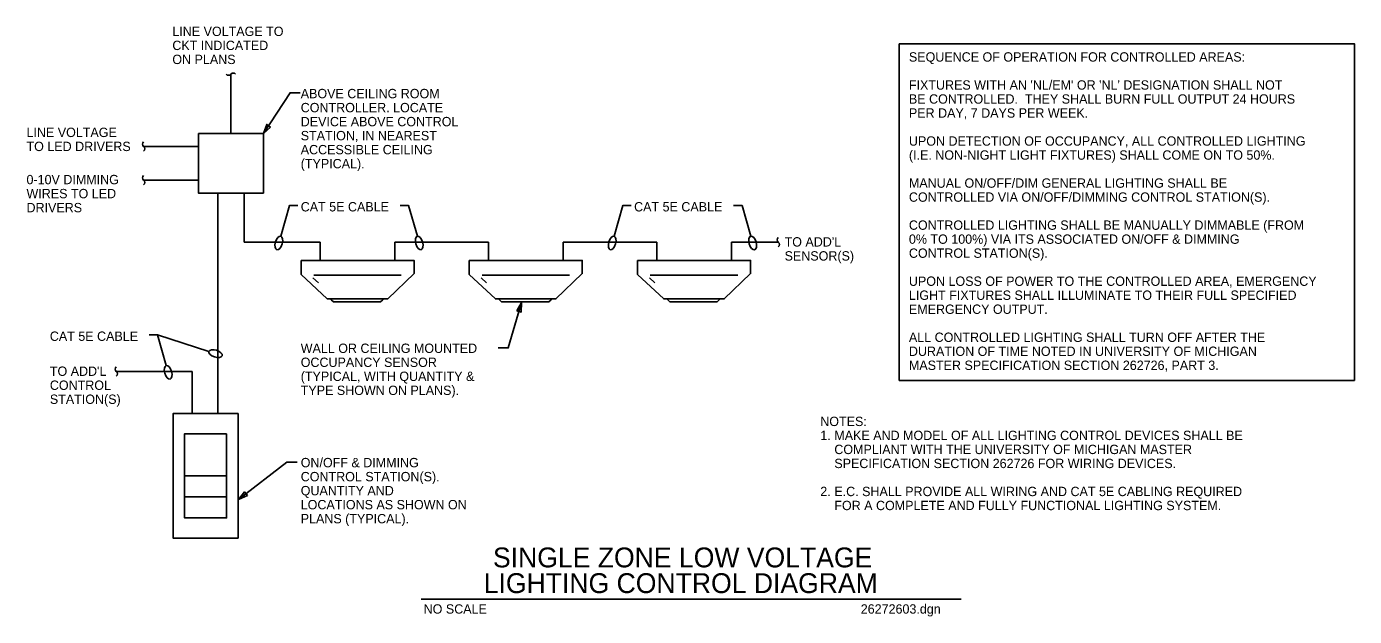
# Model space of a CAD drawing. Extents: x 10013.8 to 10108.5, y 10096.8 to 10138.9.
import ezdxf

# ---------------------------------------------------------------- set-up
doc = ezdxf.new("R2010")
doc.units = 0
for name, color, linetype in [('G-ANNO-CELL', 7, 'Continuous'), ('G-ANNO-TEXT', 7, 'Continuous'), ('G-DETL-LINE', 7, 'Continuous'), ('Level 3', 7, 'Continuous')]:
    doc.layers.add(name, color=color, linetype=linetype)

msp = doc.modelspace()

# ---------------------------------------------------------------- linework, layer by layer
at = {"layer": 'G-ANNO-CELL'}
msp.add_line((10041.898, 10098.023), (10080.422, 10098.023), dxfattribs=at)
at = {"layer": 'G-ANNO-TEXT'}
msp.add_line((10023.101, 10116.871), (10026.757, 10115.693), dxfattribs=at)
for points in [[(10075.997, 10137.655), (10108.458, 10137.655), (10108.458, 10113.63), (10075.997, 10113.63)], [(10031.167, 10131.701), (10030.653, 10131.244), (10030.892, 10131.889)], [(10048.716, 10118.601), (10049.063, 10119.194), (10049.036, 10118.508)], [(10029.513, 10105.412), (10028.885, 10105.132), (10029.308, 10105.674)]]:
    msp.add_lwpolyline(points, close=True, dxfattribs=at)
for points in [[(10033.28, 10134.151), (10032.551, 10134.151), (10030.653, 10131.244)], [(10033.106, 10126.106), (10032.505, 10126.106), (10031.885, 10123.918)], [(10040.407, 10126.106), (10041.009, 10126.106), (10041.628, 10123.918)], [(10056.882, 10126.106), (10056.281, 10126.106), (10055.661, 10123.918)], [(10064.183, 10126.106), (10064.784, 10126.106), (10065.404, 10123.918)], [(10047.402, 10115.946), (10048.112, 10115.946), (10049.063, 10119.194)], [(10022.499, 10116.871), (10023.101, 10116.871), (10023.72, 10114.683)], [(10033.054, 10107.791), (10032.325, 10107.791), (10028.885, 10105.132)]]:
    msp.add_lwpolyline(points, dxfattribs=at)
for centre, major_axis in [((10031.749, 10123.437), (-0.136, -0.481)), ((10041.764, 10123.437), (0.136, -0.481)), ((10055.525, 10123.437), (-0.136, -0.481)), ((10065.54, 10123.437), (0.136, -0.481)), ((10027.233, 10115.539), (0.476, -0.153)), ((10023.857, 10114.202), (0.136, -0.481))]:
    msp.add_ellipse(centre, major_axis=major_axis, ratio=0.5, dxfattribs=at)
at = {"layer": 'G-DETL-LINE'}
for p, q in [((10028.337, 10131.244), (10028.337, 10135.48)), ((10026.021, 10130.321), (10022.107, 10130.321)), ((10026.021, 10127.923), (10022.107, 10127.923)), ((10027.388, 10111.26), (10027.388, 10127)), ((10029.286, 10123.5), (10029.286, 10127)), ((10029.286, 10123.5), (10034.7, 10123.5)), ((10034.7, 10122.185), (10034.7, 10123.5)), ((10040.027, 10122.185), (10040.027, 10123.5)), ((10040.027, 10123.5), (10046.699, 10123.5)), ((10046.699, 10122.185), (10046.699, 10123.5)), ((10052.027, 10123.5), (10058.699, 10123.5)), ((10052.027, 10122.185), (10052.027, 10123.5)), ((10058.699, 10122.185), (10058.699, 10123.5)), ((10064.027, 10122.185), (10064.027, 10123.5)), ((10064.027, 10123.5), (10067.363, 10123.5)), ((10034.571, 10120.595), (10034.174, 10120.949)), ((10034.243, 10121.131), (10037.363, 10121.131)), ((10040.483, 10121.131), (10037.363, 10121.131)), ((10046.571, 10120.595), (10046.174, 10120.949)), ((10046.243, 10121.131), (10049.363, 10121.131)), ((10052.483, 10121.131), (10049.363, 10121.131)), ((10058.571, 10120.595), (10058.174, 10120.949)), ((10058.243, 10121.131), (10061.363, 10121.131)), ((10064.483, 10121.131), (10061.363, 10121.131)), ((10025.579, 10114.265), (10020.158, 10114.265)), ((10025.579, 10111.26), (10025.579, 10114.265)), ((10028.027, 10105.321), (10025.027, 10105.321))]:
    msp.add_line(p, q, dxfattribs=at)
for points in [[(10026.021, 10131.244), (10030.653, 10131.244), (10030.653, 10127), (10026.021, 10127)], [(10028.843, 10111.26), (10024.211, 10111.26), (10024.211, 10102.383), (10028.843, 10102.383)], [(10028.027, 10109.821), (10025.027, 10109.821), (10025.027, 10106.821), (10028.027, 10106.821)], [(10028.027, 10106.821), (10025.027, 10106.821), (10025.027, 10103.821), (10028.027, 10103.821)]]:
    msp.add_lwpolyline(points, close=True, dxfattribs=at)
for points in [[(10033.332, 10122.185), (10041.395, 10122.185), (10041.395, 10121.246), (10039.515, 10119.447), (10035.2, 10119.447), (10033.332, 10121.196), (10033.332, 10122.185)], [(10045.332, 10122.185), (10053.394, 10122.185), (10053.394, 10121.246), (10051.515, 10119.447), (10047.2, 10119.447), (10045.332, 10121.196), (10045.332, 10122.185)], [(10057.332, 10122.185), (10065.394, 10122.185), (10065.394, 10121.246), (10063.515, 10119.447), (10059.199, 10119.447), (10057.332, 10121.196), (10057.332, 10122.185)], [(10039.161, 10119.447), (10039.161, 10119.38), (10039.008, 10119.231), (10035.638, 10119.231), (10035.485, 10119.379), (10035.485, 10119.447)], [(10051.161, 10119.447), (10051.161, 10119.38), (10051.007, 10119.231), (10047.638, 10119.231), (10047.484, 10119.379), (10047.484, 10119.447)], [(10063.161, 10119.447), (10063.161, 10119.38), (10063.007, 10119.231), (10059.638, 10119.231), (10059.484, 10119.379), (10059.484, 10119.447)]]:
    msp.add_lwpolyline(points, dxfattribs=at)
for centre, start, end in [((10028.17, 10135.605), 216.8699, 323.1301), ((10028.504, 10135.355), 36.8699, 143.1301), ((10022.232, 10130.487), 126.8699, 233.1301), ((10021.982, 10130.154), 306.8699, 53.1301), ((10022.232, 10128.09), 126.8699, 233.1301), ((10021.982, 10127.757), 306.8699, 53.1301), ((10067.488, 10123.667), 126.8699, 233.1301), ((10067.238, 10123.333), 306.8699, 53.1301), ((10020.283, 10114.432), 126.8699, 233.1301), ((10020.033, 10114.099), 306.8699, 53.1301)]:
    msp.add_arc(centre, 0.208, start, end, dxfattribs=at)

# ---------------------------------------------------------------- texts
at = {"layer": 'G-ANNO-CELL'}
for s, height, p in [('SINGLE ZONE LOW VOLTAGE', 1.41667, (10047.02, 10100.289)), ('LIGHTING CONTROL DIAGRAM', 1.41667, (10046.365, 10098.455)), ('NO SCALE', 0.6667, (10042.078, 10096.988))]:
    msp.add_text(s, height=height, dxfattribs=at).set_placement(p)
at = {"layer": 'G-ANNO-TEXT'}
for s, height, p in [('LINE VOLTAGE TO ', 0.66667, (10024.156, 10138.201)), ('CKT INDICATED ', 0.66667, (10024.156, 10137.201)), ('ON PLANS', 0.6667, (10024.156, 10136.201)), ('SEQUENCE OF OPERATION FOR CONTROLLED AREAS:', 0.66667, (10076.685, 10136.376)), ("FIXTURES WITH AN 'NL/EM' OR 'NL' DESIGNATION SHALL NOT ", 0.66667, (10076.685, 10134.376)), ('ABOVE CEILING ROOM ', 0.66667, (10033.312, 10133.762)), ('BE CONTROLLED.  THEY SHALL BURN FULL OUTPUT 24 HOURS ', 0.66667, (10076.685, 10133.376)), ('CONTROLLER. LOCATE ', 0.66667, (10033.312, 10132.762)), ('PER DAY, 7 DAYS PER WEEK.', 0.66667, (10076.685, 10132.376)), ('DEVICE ABOVE CONTROL ', 0.66667, (10033.312, 10131.762)), ('LINE VOLTAGE ', 0.66667, (10013.755, 10130.993)), ('STATION, IN NEAREST ', 0.66667, (10033.312, 10130.762)), ('UPON DETECTION OF OCCUPANCY, ALL CONTROLLED LIGHTING ', 0.66667, (10076.685, 10130.376)), ('TO LED DRIVERS', 0.66667, (10013.755, 10129.993)), ('ACCESSIBLE CEILING ', 0.66667, (10033.312, 10129.762)), ('(I.E. NON-NIGHT LIGHT FIXTURES) SHALL COME ON TO 50%.', 0.66667, (10076.685, 10129.376)), ('(TYPICAL).', 0.6667, (10033.312, 10128.762)), ('0-10V DIMMING ', 0.66667, (10013.755, 10127.626)), ('WIRES TO LED ', 0.66667, (10013.755, 10126.626)), ('MANUAL ON/OFF/DIM GENERAL LIGHTING SHALL BE ', 0.66667, (10076.685, 10127.376)), ('DRIVERS ', 0.6667, (10013.755, 10125.626)), ('CAT 5E CABLE', 0.66667, (10033.312, 10125.685)), ('CAT 5E CABLE', 0.66667, (10057.087, 10125.685)), ('CONTROLLED VIA ON/OFF/DIMMING CONTROL STATION(S).', 0.66667, (10076.685, 10126.376)), ('CONTROLLED LIGHTING SHALL BE MANUALLY DIMMABLE (FROM ', 0.66667, (10076.685, 10124.376)), ("TO ADD'L ", 0.6667, (10067.82, 10123.18)), ('0% TO 100%) VIA ITS ASSOCIATED ON/OFF & DIMMING ', 0.66667, (10076.685, 10123.376)), ('SENSOR(S)', 0.6667, (10067.82, 10122.18)), ('CONTROL STATION(S).', 0.66667, (10076.685, 10122.376)), ('UPON LOSS OF POWER TO THE CONTROLLED AREA, EMERGENCY ', 0.66667, (10076.685, 10120.376)), ('LIGHT FIXTURES SHALL ILLUMINATE TO THEIR FULL SPECIFIED ', 0.66667, (10076.685, 10119.376)), ('EMERGENCY OUTPUT.', 0.66667, (10076.685, 10118.376)), ('CAT 5E CABLE', 0.66667, (10015.419, 10116.45)), ('ALL CONTROLLED LIGHTING SHALL TURN OFF AFTER THE ', 0.66667, (10076.685, 10116.376)), ('WALL OR CEILING MOUNTED ', 0.66667, (10033.312, 10115.589)), ('DURATION OF TIME NOTED IN UNIVERSITY OF MICHIGAN ', 0.66667, (10076.685, 10115.376)), ('OCCUPANCY SENSOR ', 0.66667, (10033.312, 10114.589)), ('MASTER SPECIFICATION SECTION 262726, PART 3.', 0.66667, (10076.685, 10114.376)), ("TO ADD'L ", 0.6667, (10015.421, 10113.953)), ('(TYPICAL, WITH QUANTITY & ', 0.66667, (10033.312, 10113.589)), ('CONTROL ', 0.6667, (10015.421, 10112.953)), ('TYPE SHOWN ON PLANS).', 0.66667, (10033.312, 10112.589)), ('STATION(S)', 0.6667, (10015.421, 10111.953)), ('NOTES:', 0.6667, (10070.363, 10110.372)), ('1.', 0.6667, (10070.363, 10109.372)), ('MAKE AND MODEL OF ALL LIGHTING CONTROL DEVICES SHALL BE ', 0.66667, (10071.366, 10109.372)), ('COMPLIANT WITH THE UNIVERSITY OF MICHIGAN MASTER ', 0.66667, (10071.366, 10108.372)), ('ON/OFF & DIMMING ', 0.66667, (10033.312, 10107.431)), ('SPECIFICATION SECTION 262726 FOR WIRING DEVICES.', 0.66667, (10071.366, 10107.372)), ('CONTROL STATION(S). ', 0.66667, (10033.312, 10106.431)), ('QUANTITY AND ', 0.66667, (10033.312, 10105.431)), ('2.', 0.6667, (10070.363, 10105.372)), ('E.C. SHALL PROVIDE ALL WIRING AND CAT 5E CABLING REQUIRED ', 0.66667, (10071.366, 10105.372)), ('LOCATIONS AS SHOWN ON ', 0.66667, (10033.312, 10104.431)), ('FOR A COMPLETE AND FULLY FUNCTIONAL LIGHTING SYSTEM.', 0.66667, (10071.366, 10104.372)), ('PLANS (TYPICAL).', 0.66667, (10033.312, 10103.431))]:
    msp.add_text(s, height=height, dxfattribs=at).set_placement(p)
at = {"layer": 'Level 3'}
msp.add_text('26272603.dgn', height=0.66667, dxfattribs=at).set_placement((10073.251, 10096.988))

doc.saveas('drawing.dxf')
